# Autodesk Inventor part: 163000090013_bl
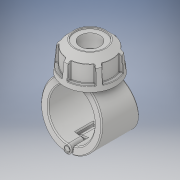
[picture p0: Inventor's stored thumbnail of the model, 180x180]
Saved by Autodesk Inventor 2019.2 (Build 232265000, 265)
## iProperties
Created: 2022-02
Part Number: 163000090013_bl
Material: Generic
Description: Plassadle Threaded 90x1 1/4''
Document SubType Name: Modeling
Designer: comp2
Density: 1 g/cm^3
Appearance: Default
Author: comp2
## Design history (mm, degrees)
derived "16300.ipt"
feature "Solid1::16300.ipt" dims "ScaleForDerivedMember" = 10
feature "Solid2::16300.ipt" dims "ScaleForDerivedMember" = 10
feature "Solid3::16300.ipt" dims "ScaleForDerivedMember" = 10
feature "Solid4::16300.ipt" dims "ScaleForDerivedMember" = 10
tag "TaggingFeature1"
body "Solid1"
body "Solid2"
body "Solid3"
body "Solid4"
other parameters: "d2" = 119 [user parameter], "d3" = 45 [user parameter], "d7" = 113.05 [user parameter], "d8" = 85 deg [user parameter], "d9" = 45 deg [user parameter], "d10" = 102 [user parameter], "d11" = 49 [user parameter], "d12" = 38.2165 [user parameter], "d13" = 42.84 [user parameter], "d14" = 58.428 [user parameter], "d42" = 2.9 [user parameter], "d49" = 2.38 [user parameter], "d50" = 94 [user parameter], "d51" = 0 [user parameter], "d52" = 20.3 [user parameter], "d53" = 65.45 [user parameter], "d54" = 32.9 [user parameter], "d55" = 0 [user parameter], "d56" = 18.8 [user parameter], "d57" = 18.8 [user parameter], "d59" = 0 [user parameter], "d60" = 94 [user parameter], "d61" = 0 [user parameter], "d62" = 32.9 [user parameter], "d63" = 0 [user parameter], "d65" = 0 [user parameter], "d67" = 0 [user parameter], "d69" = 0 [user parameter], "d70" = 1 [user parameter], "d71" = 90.24 [user parameter], "d72" = 0 [user parameter], "d73" = 2 [user parameter], "d78" = 86.7 [user parameter], "d79" = 5.1 [user parameter], "d80" = 60 deg [user parameter], "d81" = 5.1 [user parameter], "d84" = 0 [user parameter], "d85" = 1 [user parameter], "d87" = 360 deg [user parameter], "d122" = 58 [user parameter], "d124" = 42.80128 [user parameter], "d125" = 2.72975 [user parameter], "d127" = 173 [user parameter], "d129" = 38.952 [user parameter], "d130" = 33.1092 [user parameter], "d131" = 37.7 [user parameter], "d132" = 45 deg [user parameter], "d133" = 26.39 [user parameter], "d134" = 19.476 [user parameter], "d136" = 0 [user parameter], "d138" = 0 [user parameter], "d1" = 25 [user parameter], "B" = 119 [user parameter], "L" = 94 [user parameter], "E_" = 54 [user parameter], "E1" = 102 [user parameter], "H1" = 173 [user parameter], "H2" = 58 [user parameter], "H3" = 78 [user parameter], "H_costum" = 49 [user parameter], "Rp" = 38.952 [user parameter], "d128" = 54.595 [user parameter]
